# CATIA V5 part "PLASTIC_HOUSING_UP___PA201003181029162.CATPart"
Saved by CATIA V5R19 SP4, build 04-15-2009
Part number: PLASTIC_HOUSING_UP___PA201003181029162
Bounding box of the stored display mesh (mm): x -26 to 26, y -20.64 to 95, z -0.5 to 11
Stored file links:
  E:\CadInnWork\InWork\PLASTIC_HOUSING_UP___PA201003181029162.CATPart
  C:\Documents and Settings\moren\Bureau\3D models\Lampe\CATIA_V5\pocket_lamp.CATProduct
  C:\Documents and Settings\moren\Bureau\3D models\Lampe\CATIA_V5\switch.CATPart
  C:\Documents and Settings\moren\Bureau\3D models\Lampe\CATIA_V5\led.CATPart
  C:\Documents and Settings\moren\Bureau\3D models\Lampe\CATIA_V5\insert.CATPart
  C:\Documents and Settings\moren\Bureau\3D models\Lampe\CATIA_V5\battery_holder.CATPart
  C:\Documents and Settings\moren\Bureau\3D models\Lampe\CATIA_V5\printed_circuit_board.CATPart
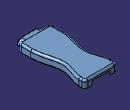
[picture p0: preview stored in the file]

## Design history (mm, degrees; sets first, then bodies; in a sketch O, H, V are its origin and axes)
Parameters
  Update = false
  PDM_version = "A"
  PDM_iteration = 1
  PDM_owner = "moren                    "
  PDM_comment = ""
  PDM_partnumber = "PA002170EA6A57201003181029160002"
Set1
  DatumCurve1: linked copy from another document
  Plane1: linked copy from another document
  DatumCurve2: linked copy from another document
  DatumCurve3: linked copy from another document
  DatumSurface1: linked copy from another document
  Plane2: linked copy from another document
  DatumCurve4: linked copy from another document
  DatumCurve5: linked copy from another document
  DatumSurface2: linked copy from another document
  DatumCurve6: linked copy from another document
  DatumCurve7: linked copy from another document
Body1 (main body)
  Sketch1 on xy-plane, origin (0, 0, 0), H (1, 0, 0), V (0, 1, 0)
    point P1 (0, -10.14)
    line L1 (0, -10.14) -> (-21, -10.14)
    point P2 (-24, -10.14)
    line L2 (0, 93) -> (-21, 93)
    line L3 (-24, 90) -> (-24, 85.2347)
    point P4 (-24, -10.14)
    reference projected line E1 (-14.9, -10.14) -> (-9.5, -10.14) from edge of DatumCurve2
    reference projected circle E2 centre (-20, 89) radius 2.5 from edge of DatumCurve3
    arc A1 centre (-21, 90) radius 3 from (-21, 93) to (-24, 90) ccw
    arc A2 centre (-21, -7.14) radius 3 from (-21, -10.14) to (-24, -7.14) cw
    line L4 (0, 93) -> (0, -10.14)
    spline S1 through (-24, 8.6583) (-20.9977, 71.7619) (-24, 85.2347)
    reference intersected line E3 through (0, 0) direction (0, 1) from Plane2
    line L5 (-24, 8.6583) -> (-24, -7.14)
    point P11 (-24, 85.2347)
    point P12 (-24, 8.6583)
    reference projected line E4 (-13.2, 95) -> (13.2, 95) from DatumCurve1
    point P13 (-24, 8.6583)
    point P14 (-24, 85.2347)
    distance E2 L3 = 1.5
    radius A1 = 3
    radius A2 = 3
    distance S1 E3 = 16.5
    distance L2 E4 = 2
    coincidence: P1 V, P4 P2, L1 E1, L1 P2, L3 P4, P13 L3, P14 L3, P14 P11, P13 P12, L3 L5
    horizontal: L1 H, L2 H
    vertical: L3 V, L4 V, L5 V
    tangency: A1 L2, A1 L3, A2 L1, A2 L3
  Pad1: profile Sketch1, direction (0, 0, 1), up to face of DatumSurface1
  Thickness1: Thickness 1, Face end face of Pad1
  Fillet1: radius 1, on edge [end face of Pad1 | face of Pad1 from Sketch1.S1]
  Shell1: IntOffset 0, Face (start face of Pad1; face of Pad1 from Sketch1.L4), ExtOffset 2
  Sketch2 on end face of Pad1, origin (0, 0, 9), H (1, 0, 0), V (0, -1, 0)
    circle A1 centre (-20, 6.14) radius 4.5
    circle A2 centre (-20, 6.14) radius 2.4
    radius A2 = 2.4
    distance A2 A1 = 2.1
  Pad2: profile Sketch2, direction (0, 0, -1), length 6.5
  Fillet2: radius 0.5, on edge [end face of Pad1 | face of Pad2 from Sketch2.A1]; edge [face of Pad1 from Sketch1.A2 | end face of Pad2]; edge [face of Pad2 from Sketch2.A1 | end face of Pad2]
  Sketch3 on end face of Pad1, origin (0, 0, 9), H (1, 0, 0), V (0, -1, 0)
    circle A1 centre (-20, -89) radius 2.4
    reference projected circle E1 centre (-20, -89) radius 2.5 from edge of DatumCurve3
    circle A2 centre (-20, -89) radius 4.5
    radius A1 = 2.4
    distance A1 A2 = 2.1
    concentricity: A1 E1
  Pad3: profile Sketch3, direction (0, 0, -1), length 6.5
  Fillet3: radius 0.5, on edge [end face of Pad1 | face of Pad3 from Sketch3.A2]; edge [face of Pad1 from Sketch1.A1 | end face of Pad3]; edge [face of Pad3 from Sketch3.A2 | end face of Pad3]
  Sketch4 on end face of Pad1, origin (0, 0, 9), H (1, 0, 0), V (0, -1, 0)
    point P1 (0, 0.2)
    line L1 (0, 0.2) -> (-16, 0.2)
    line L2 (-16, 0.2) -> (-16, -1.2)
    line L3 (-16, -1.2) -> (0, -1.2)
    point P4 (0, -1.2)
    reference projected line E1 (15, -1) -> (-15, -1) from edge of DatumCurve5
    reference intersected line E2 through (0, 0) direction (-1, 0) from face of DatumSurface2
    reference projected line E3 (-15, 0) -> (-15, -1) from edge of DatumCurve6
    line L4 (0, -1.2) -> (0, -2.95)
    line L5 (0, -2.95) -> (-15.8, -2.95)
    line L6 (-17.75, -27.95) -> (-17.75, -0.05)
    line L7 (-15.75, 1.95) -> (0, 1.95)
    point P6 (0, 1.95)
    line L8 (0, 1.95) -> (0, 0.2)
    arc A1 centre (-15.75, -0.05) radius 2 from (-15.75, 1.95) to (-17.75, -0.05) ccw
    point P10 (-17.75, -27.95)
    line L9 (-16, -3.15) -> (-16, -27.95)
    line L10 (-16, -27.95) -> (-17.75, -27.95)
    point P12 (-17.75, -27.95)
    arc A2 centre (-15.8, -3.15) radius 0.2 from (-15.8, -2.95) to (-16, -3.15) ccw
    distance E1 L3 = 0.2
    distance L1 E2 = 0.2
    distance E3 L2 = 1
    distance L1 L7 = 1.75
    distance L2 L6 = 1.75
    distance L5 L3 = 1.75
    radius A1 = 2
    distance L9 L6 = 1.75
    radius A2 = 0.2
    distance L10 L5 = 25
    coincidence: P1 V, P4 V, P6 V, P12 L6, P10 P12
    horizontal: L1 H, L3 H, L5 H, L7 H, L10 H
    vertical: L2 V, L4 V, L6 V, L8 V, L9 V
    tangency: A1 L7, A1 L6, A2 L5, A2 L9
  Pad4: profile Sketch4, direction (0, 0, -1), length 7.5
  Fillet4: radius 0.5, on edge [face of Pad4 from Sketch4.L5 | end face of Pad1]; edge [face of Pad4 from Sketch4.L6 | end face of Pad1]; edge [face of Pad4 from Sketch4.L10 | end face of Pad1]; edge [face of Pad4 from Sketch4.L9 | face of Pad4 from Sketch4.L10]; edge [face of Pad4 from Sketch4.L10 | face of Pad4 from Sketch4.L6]; edge [end face of Pad4 | face of Pad4 from Sketch4.L6]; edge [end face of Pad4 | face of Pad4 from Sketch4.L9]; edge [end face of Pad4 | face of Pad4 from Sketch4.L3]; edge [end face of Pad4 | face of Pad4 from Sketch4.L2]; edge [end face of Pad4 | face of Pad4 from Sketch4.L1]; edge [face of Pad4 from Sketch4.L1 | face of Pad4 from Sketch4.L2]; edge [face of Pad4 from Sketch4.L2 | face of Pad4 from Sketch4.L3]
  Sketch5 on end face of Pad1, origin (0, 0, 9), H (1, 0, 0), V (0, -1, 0)
    point P1 (0, -64)
    line L1 (0, -64) -> (-19.3403, -64)
    line L2 (-19.3403, -64) -> (-20.1053, -65.75)
    line L3 (-20.1053, -65.75) -> (0, -65.75)
    point P4 (0, -65.75)
    line L4 (0, -65.75) -> (0, -64)
    reference projected line E1 (-10, -64) -> (10, -64) from edge of DatumCurve7
    distance L1 L3 = 1.75
    coincidence: P1 V, P4 V, L1 E1
    horizontal: L1 H, L3 H
    vertical: L4 V
  Pad5: profile Sketch5, direction (0, 0, -1), length 7.5
  Fillet5: radius 0.5, on edge [end face of Pad1 | face of Pad5 from Sketch5.L3]; edge [end face of Pad5 | face of Pad1 from Sketch1.S1]; edge [face of Pad5 from Sketch5.L3 | end face of Pad5]; edge [face of Pad5 from Sketch5.L1 | end face of Pad5]
  Sketch6 on face of Shell1, origin (0, 95, 0), H (-1, 0, 0), V (0, 0, 1)
    line L1 (0, 0) -> (15.025, 0)
    line L2 (15.025, 0) -> (15.025, 5.525)
    line L3 (15.025, 5.525) -> (0, 5.525)
    line L4 (0, 5.525) -> (0, 0)
    length L2 = 5.525
    length L3 = 15.025
    horizontal: L1 H, L3 H
    vertical: L2 V, L4 V
  Pocket1: profile Sketch6, direction (0, -1, 0), through (limit type 6)
  Sketch7 on face of Shell1, origin (0, -12.14, 0), H (1, 0, 0), V (0, 0, 1)
    circle A1 centre (-12, 0) radius 2.5
    reference projected arc E1 centre (-12, 0) radius 2.9 from (-9.5, 1.4697) to (-9.5, -1.4697) ccw from edge of DatumCurve2
    radius A1 = 2.5
    concentricity: A1 E1
  Pocket2: profile Sketch7, direction (0, 1, 0), up to face of Pad1 from Sketch1.L1
  RectPattern1: of Pocket2, direction 1 instances 3, spacing 6, along edge [face of Shell1 | start face of Pad1] reversed
  Sketch8 on face of Shell1, origin (0, -12.14, 0), H (1, 0, 0), V (0, 0, 1)
    point P1 (0, 4.9)
    line L1 (0, 4.9) -> (-12, 4.9)
    point P2 (-12, 4.9)
    spline S1 through (-12, 4.9) (-16.9, 0)
    construction line L2 (-12, 4.9) -> (-12, 0)
    point P4 (-12, 4.9)
    point P5 (-16.9, 0)
    coincidence: P1 V, P4 P2, P5 H
    horizontal: L1 H
    vertical: L2 V
  Pad6: profile Sketch8, direction (0, -1, 0), length 7.5, thin wall 0, second thickness 2
  Fillet6: radius 0.5, on edge [face of Shell1 | face of Pad6]; edge [face of Pad6 | face of Shell1]
  Sketch9 on end face of Pad6, origin (0, -19.64, 0), H (1, 0, 0), V (0, 0, 1)
    point P1 (-18.9, 0)
    line L1 (-18.9, 0) -> (-18.9, -0.5)
    line L2 (-18.9, -0.5) -> (-18.025, -0.5)
    line L3 (-18.025, -0.5) -> (-18.025, 0)
    point P4 (-18.025, 0)
    reference projected point E1 (-18.9, 0) from Sketch10.E1
    reference intersected line E2 through (0, 0) direction (-1, 0) from face of Pad6
    line L4 (-18.025, 0) -> (-18.9, 0)
    length L1 = 0.5
    length L2 = 0.875
    vertical: L1 V, L3 V
    horizontal: L2 H, L4 H
    coincidence: P1 E1, P4 E2
  Sketch10 on face of Pad6, origin (0, 0, 0), H (1, 0, 0), V (0, -1, 0)
    projected line E1 (-18.9, 12.64) -> (-18.9, 19.64) from edge [face of Pad6 | face of Pad6]
    projected arc E2 centre (-19.4, 12.64) radius 0.5 from (-19.4, 12.14) to (-18.9, 12.64) ccw from edge [face of Fillet6 | face of Pad6]
    projected line E3 (-19.4, 12.14) -> (-21, 12.14) from edge [face of Shell1 | face of Pad6]
    projected arc E4 centre (-21, 7.14) radius 5 from (-21, 12.14) to (-26, 7.14) ccw from edge [face of Pad6 | face of Shell1]
    projected line E5 (-26, -8.6583) -> (-26, 7.14) from edge [face of Pad6 | face of Shell1]
    projected curve E6 from edge [face of Pad6 | face of Shell1]
    projected line E7 (-26, -90) -> (-26, -85.2347) from edge [face of Pad6 | face of Shell1]
    projected arc E8 centre (-21, -90) radius 5 from (-26, -90) to (-21, -95) ccw from edge [face of Pad6 | face of Shell1]
    projected line E9 (-15.025, -95) -> (-21, -95) from edge [face of Pad6 | face of Shell1]
  Rib1: profile Sketch9, centre curve Sketch10
  Mirror1: of the body so far, about yz-plane
  Sketch11 on face of Pad6, origin (0, 0, 0), H (1, 0, 0), V (0, -1, 0)
    point P1 (-16.9, 19.64)
    line L1 (-16.9, 19.64) -> (-17.9, 19.64)
    line L2 (-17.9, 19.64) -> (-17.9, 18.64)
    line L3 (-17.9, 18.64) -> (-16.9, 18.64)
    line L4 (-16.9, 18.64) -> (-16.9, 19.64)
    reference projected point E1 (-16.9, 19.64) from Sketch12.P6
    length L1 = 1
    length L4 = 1
    horizontal: L1 H, L3 H
    vertical: L2 V, L4 V
    coincidence: P1 E1
  Sketch12 on face of Rib1, origin (0, -19.64, 0), H (1, 0, 0), V (0, 0, 1)
    projected curve E1 from edge [face of Mirror1 | face of Rib1]
    projected line E2 (-12, 4.9) -> (12, 4.9) from edge [face of Pad6 | face of Rib1]
    projected curve E3 from edge [face of Rib1 | face of Pad6]
    point P6 (-16.9, 0)
  Slot1: profile Sketch11, centre curve Sketch12
  Sketch13 on face of Rib1, origin (0, -19.64, 0), H (1, 0, 0), V (0, 0, 1)
    projected curve E1 from edge [face of Rib1 | face of Mirror1]
    projected line E2 (-12, 6.9) -> (12, 6.9) from edge [face of Rib1 | face of Pad6]
    projected curve E3 from edge [face of Pad6 | face of Rib1]
    projected curve E4 from edge [face of Slot1 | face of Mirror1]
    projected line E5 (-12, 4.9) -> (12, 4.9) from edge [face of Pad6 | face of Slot1]
    projected curve E6 from edge [face of Slot1 | face of Pad6]
    line L1 (-18.025, 0) -> (-16.9, 0)
    line L2 (18.9, 0) -> (18.9, -0.5)
    point P13 (18.9, -0.5)
    reference projected point E7 (18.9, -0.5) from vertex [face of Mirror1 | face of Mirror1 | face of Mirror1]
    line L3 (18.9, -0.5) -> (18.025, -0.5)
    line L4 (18.025, -0.5) -> (18.025, 0)
    point P15 (18.025, 0)
    line L5 (18.025, 0) -> (16.9, 0)
    reference projected line E8 (18.025, -0.5) -> (18.025, 0) from edge [face of Mirror1 | face of Mirror1]
    line L6 (-18.9, 0) -> (-18.9, -0.5)
    line L7 (-18.9, -0.5) -> (-18.025, -0.5)
    line L8 (-18.025, -0.5) -> (-18.025, 0)
    reference projected line E9 (-18.9, -0.5) -> (-18.025, -0.5) from edge [face of Rib1 | face of Rib1]
    reference projected line E10 (-18.025, -0.5) -> (-18.025, 0) from edge [face of Rib1 | face of Rib1]
    horizontal: L1 H, L3 H, L5 H, L7 H
    vertical: L2 V, L4 V, L6 V
    coincidence: P13 E7, P15 H, L4 E8, L7 E9, L8 E10
  Pad7: profile Sketch13, direction (0, -1, 0), length 1
  Fillet7: radius 0.5, on edge [face of Pad7 from Sketch13.E1 | end face of Pad7]; edge [face of Pad7 from Sketch13.E4 | end face of Pad7]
